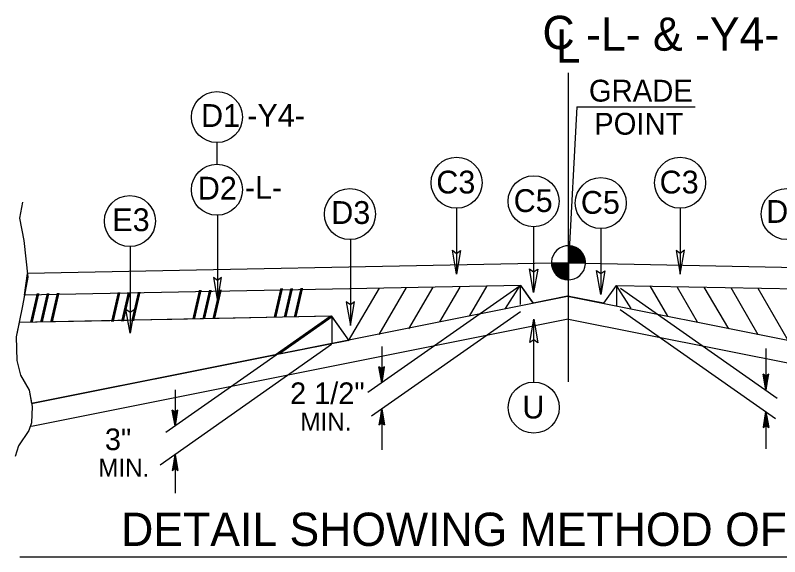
# Model space of a CAD drawing. Extents: x 1904401 to 1905163, y 193929 to 194736.
# Drawn here: x 1904976.61 to 1905019.98, y 194607.17 to 194637.9 of the extents above; entities that cross this region are included whole.
import ezdxf

# ---------------------------------------------------------------- set-up
doc = ezdxf.new("R2010")
doc.units = 0
for name, color, linetype in [('Old_Level_1', 7, 'Continuous'), ('Old_Level_11', 7, 'Continuous'), ('Old_Level_2', 7, 'Continuous'), ('Old_Level_20', 7, 'Continuous'), ('Old_Level_21', 7, 'Continuous'), ('Old_Level_3', 7, 'Continuous'), ('Prop Shade Medium', 7, 'Continuous')]:
    doc.layers.add(name, color=color, linetype=linetype)

msp = doc.modelspace()

# ---------------------------------------------------------------- linework, layer by layer
at = {"layer": 'Old_Level_1'}
for p, q in [((1905007.984, 194617.085), (1905007.984, 194634.631)), ((1905007.991, 194623.852), (1905007.991, 194624.817)), ((1905007.024, 194623.852), (1905007.991, 194623.852)), ((1905007.991, 194623.852), (1905007.991, 194622.885)), ((1905008.959, 194623.852), (1905007.991, 194623.852)), ((1905007.991, 194622.885), (1905007.991, 194623.852)), ((1905007.985, 194622.885), (1905007.985, 194623.841)), ((1905005.257, 194622.546), (1904996.612, 194616.491)), ((1904997.244, 194622.408), (1904995.5, 194619.42)), ((1904998.775, 194622.44), (1904997.232, 194619.789)), ((1905000.291, 194622.469), (1904998.906, 194620.095)), ((1905001.819, 194622.466), (1905000.671, 194620.5)), ((1905003.358, 194622.545), (1905002.358, 194620.829)), ((1905010.934, 194622.406), (1905019.841, 194616.168)), ((1905012.61, 194622.545), (1905013.612, 194620.829)), ((1905014.15, 194622.466), (1905015.298, 194620.5)), ((1905015.677, 194622.469), (1905017.064, 194620.095)), ((1905017.194, 194622.44), (1905018.738, 194619.789)), ((1905018.726, 194622.408), (1905020.444, 194619.464)), ((1904994.56, 194620.816), (1904976.825, 194620.461)), ((1904994.56, 194620.816), (1904985.144, 194614.222)), ((1904995.525, 194619.461), (1904994.56, 194620.816)), ((1904994.56, 194620.816), (1904994.56, 194619.269)), ((1905005.278, 194621.067), (1904996.817, 194615.143)), ((1905010.922, 194621.193), (1905019.742, 194615.018)), ((1905007.973, 194620.653), (1904977.518, 194614.562)), ((1905007.996, 194620.653), (1905038.521, 194614.547)), ((1904994.553, 194619.22), (1904984.818, 194612.369)), ((1904994.56, 194619.271), (1904991.472, 194618.653)), ((1904997.399, 194619.1), (1904997.399, 194617.044)), ((1904991.472, 194618.653), (1904977.529, 194615.864)), ((1905019.19, 194618.982), (1905019.19, 194616.625)), ((1904997.399, 194617.044), (1904997.24, 194617.946)), ((1904997.399, 194617.828), (1904997.24, 194617.946)), ((1904997.399, 194617.044), (1904997.263, 194617.929)), ((1904997.285, 194617.911), (1904997.399, 194617.044)), ((1904997.399, 194617.044), (1904997.308, 194617.896)), ((1904997.331, 194617.879), (1904997.399, 194617.044)), ((1904997.399, 194617.044), (1904997.354, 194617.862)), ((1904997.377, 194617.845), (1904997.399, 194617.044)), ((1904997.399, 194617.044), (1904997.559, 194617.946)), ((1904997.559, 194617.946), (1904997.399, 194617.828)), ((1904997.537, 194617.929), (1904997.399, 194617.044)), ((1904997.399, 194617.044), (1904997.512, 194617.911)), ((1904997.489, 194617.896), (1904997.399, 194617.044)), ((1904997.399, 194617.044), (1904997.467, 194617.879)), ((1904997.444, 194617.862), (1904997.399, 194617.044)), ((1904997.399, 194617.044), (1904997.421, 194617.845)), ((1904997.399, 194617.828), (1904997.399, 194617.044)), ((1905019.19, 194616.625), (1905019.032, 194617.527)), ((1905019.19, 194617.409), (1905019.032, 194617.527)), ((1905019.19, 194616.625), (1905019.053, 194617.51)), ((1905019.076, 194617.493), (1905019.19, 194616.625)), ((1905019.19, 194616.625), (1905019.099, 194617.476)), ((1905019.122, 194617.459), (1905019.19, 194616.625)), ((1905019.19, 194616.625), (1905019.144, 194617.443)), ((1905019.166, 194617.427), (1905019.19, 194616.625)), ((1905019.19, 194616.625), (1905019.35, 194617.527)), ((1905019.35, 194617.527), (1905019.19, 194617.409)), ((1905019.326, 194617.51), (1905019.19, 194616.625)), ((1905019.19, 194616.625), (1905019.303, 194617.493)), ((1905019.281, 194617.476), (1905019.19, 194616.625)), ((1905019.19, 194616.625), (1905019.258, 194617.459)), ((1905019.235, 194617.443), (1905019.19, 194616.625)), ((1905019.19, 194616.625), (1905019.214, 194617.427)), ((1905019.19, 194617.409), (1905019.19, 194616.625)), ((1904985.674, 194616.642), (1904985.674, 194614.591)), ((1904985.674, 194614.591), (1904985.513, 194615.494)), ((1904985.674, 194615.378), (1904985.513, 194615.494)), ((1904985.674, 194614.591), (1904985.536, 194615.478)), ((1904985.561, 194615.46), (1904985.674, 194614.591)), ((1904985.674, 194614.591), (1904985.584, 194615.444)), ((1904985.606, 194615.428), (1904985.674, 194614.591)), ((1904985.674, 194614.591), (1904985.628, 194615.412)), ((1904985.651, 194615.395), (1904985.674, 194614.591)), ((1904985.674, 194614.591), (1904985.833, 194615.494)), ((1904985.833, 194615.494), (1904985.674, 194615.378)), ((1904985.81, 194615.478), (1904985.674, 194614.591)), ((1904985.674, 194614.591), (1904985.788, 194615.46)), ((1904985.765, 194615.444), (1904985.674, 194614.591)), ((1904985.674, 194614.591), (1904985.741, 194615.428)), ((1904985.72, 194615.412), (1904985.674, 194614.591)), ((1904985.674, 194614.591), (1904985.697, 194615.395)), ((1904985.674, 194615.378), (1904985.674, 194614.591)), ((1904997.399, 194615.551), (1904997.24, 194614.648)), ((1904997.263, 194614.666), (1904997.399, 194615.551)), ((1904997.399, 194615.551), (1904997.285, 194614.682)), ((1904997.308, 194614.7), (1904997.399, 194615.551)), ((1904997.399, 194615.551), (1904997.331, 194614.716)), ((1904997.354, 194614.732), (1904997.399, 194615.551)), ((1904997.399, 194615.551), (1904997.377, 194614.749)), ((1904997.399, 194615.551), (1904997.399, 194613.234)), ((1904997.399, 194615.551), (1904997.559, 194614.648)), ((1904997.399, 194614.765), (1904997.399, 194615.551)), ((1904997.421, 194614.749), (1904997.399, 194615.551)), ((1904997.399, 194615.551), (1904997.444, 194614.732)), ((1904997.467, 194614.716), (1904997.399, 194615.551)), ((1904997.399, 194615.551), (1904997.489, 194614.7)), ((1904997.512, 194614.682), (1904997.399, 194615.551)), ((1904997.399, 194615.551), (1904997.537, 194614.666)), ((1905019.19, 194615.404), (1905019.032, 194614.501)), ((1905019.053, 194614.52), (1905019.19, 194615.404)), ((1905019.19, 194615.404), (1905019.076, 194614.535)), ((1905019.099, 194614.553), (1905019.19, 194615.404)), ((1905019.19, 194615.404), (1905019.122, 194614.569)), ((1905019.144, 194614.585), (1905019.19, 194615.404)), ((1905019.19, 194615.404), (1905019.166, 194614.601)), ((1905019.19, 194615.404), (1905019.19, 194613.294)), ((1905019.19, 194615.404), (1905019.35, 194614.501)), ((1905019.19, 194614.619), (1905019.19, 194615.404)), ((1905019.214, 194614.601), (1905019.19, 194615.404)), ((1905019.19, 194615.404), (1905019.235, 194614.585)), ((1905019.258, 194614.569), (1905019.19, 194615.404)), ((1905019.19, 194615.404), (1905019.281, 194614.553)), ((1905019.303, 194614.535), (1905019.19, 194615.404)), ((1905019.19, 194615.404), (1905019.326, 194614.52)), ((1904997.24, 194614.648), (1904997.399, 194614.765)), ((1904997.399, 194614.765), (1904997.559, 194614.648)), ((1905019.032, 194614.501), (1905019.19, 194614.619)), ((1905019.19, 194614.619), (1905019.35, 194614.501)), ((1904985.674, 194612.97), (1904985.513, 194612.067)), ((1904985.538, 194612.084), (1904985.674, 194612.97)), ((1904985.674, 194612.97), (1904985.561, 194612.101)), ((1904985.584, 194612.117), (1904985.674, 194612.97)), ((1904985.674, 194612.97), (1904985.606, 194612.134)), ((1904985.628, 194612.15), (1904985.674, 194612.97)), ((1904985.674, 194612.97), (1904985.651, 194612.167)), ((1904985.674, 194612.97), (1904985.674, 194610.776)), ((1904985.674, 194612.97), (1904985.833, 194612.067)), ((1904985.674, 194612.184), (1904985.674, 194612.97)), ((1904985.697, 194612.167), (1904985.674, 194612.97)), ((1904985.674, 194612.97), (1904985.72, 194612.15)), ((1904985.743, 194612.134), (1904985.674, 194612.97)), ((1904985.674, 194612.97), (1904985.765, 194612.117)), ((1904985.788, 194612.101), (1904985.674, 194612.97)), ((1904985.674, 194612.97), (1904985.81, 194612.084)), ((1904985.513, 194612.067), (1904985.674, 194612.184)), ((1904985.674, 194612.184), (1904985.833, 194612.067))]:
    msp.add_line(p, q, dxfattribs=at)
for points in [[(1904977.013, 194627.289), (1904976.85, 194626.39), (1904977.096, 194625.112), (1904977.312, 194623.043), (1904977.013, 194621.41), (1904976.66, 194619.641), (1904976.687, 194618.307), (1904976.905, 194617.464), (1904977.396, 194616.619), (1904977.558, 194615.694), (1904977.531, 194614.769), (1904977.368, 194614.332), (1904976.797, 194613.461), (1904976.606, 194612.862)], [(1905008, 194624.817), (1905008, 194624.817), (1905008, 194623.852)], [(1905008.019, 194624.817), (1905008.019, 194623.852)], [(1905008.039, 194624.817), (1905008.039, 194623.852)], [(1905008.058, 194624.816), (1905008.058, 194623.852)], [(1905008.079, 194624.815), (1905008.079, 194623.852)], [(1905008.097, 194624.812), (1905008.097, 194623.852)], [(1905008.117, 194624.811), (1905008.117, 194623.852)], [(1905008.135, 194624.807), (1905008.135, 194623.852)], [(1905008.155, 194624.804), (1905008.155, 194623.852)], [(1905008.174, 194624.8), (1905008.174, 194623.852)], [(1905008.194, 194624.798), (1905008.194, 194623.852)], [(1905008.214, 194624.793), (1905008.214, 194623.852)], [(1905008.233, 194624.788), (1905008.233, 194623.852)], [(1905008.252, 194624.782), (1905008.252, 194623.852)], [(1905008.27, 194624.777), (1905008.27, 194623.852)], [(1905008.289, 194624.771), (1905008.289, 194623.852)], [(1905008.31, 194624.764), (1905008.31, 194623.852)], [(1905008.33, 194624.758), (1905008.33, 194623.852)], [(1905008.349, 194624.75), (1905008.349, 194623.852)], [(1905008.369, 194624.742), (1905008.367, 194623.852)], [(1905008.388, 194624.733), (1905008.388, 194623.852)], [(1905008.406, 194624.725), (1905008.406, 194623.852)], [(1905008.425, 194624.716), (1905008.425, 194623.852)], [(1905008.445, 194624.705), (1905008.445, 194623.852)], [(1905008.464, 194624.693), (1905008.464, 194623.852)], [(1905008.485, 194624.682), (1905008.485, 194623.852)], [(1905008.504, 194624.671), (1905008.503, 194623.852)], [(1905008.523, 194624.66), (1905008.523, 194623.852)], [(1905008.541, 194624.646), (1905008.541, 194623.852)], [(1905008.56, 194624.632), (1905008.56, 194623.852)], [(1905008.581, 194624.618), (1905008.581, 194623.852)], [(1905008.6, 194624.603), (1905008.6, 194623.852)], [(1905008.62, 194624.586), (1905008.62, 194623.852)], [(1905008.639, 194624.57), (1905008.638, 194623.851)], [(1905008.659, 194624.551), (1905008.659, 194623.852)], [(1905008.676, 194624.533), (1905008.676, 194623.851)], [(1905008.696, 194624.512), (1905008.696, 194623.851)], [(1905008.716, 194624.49), (1905008.716, 194623.852)], [(1905008.735, 194624.468), (1905008.735, 194623.851)], [(1905008.756, 194624.444), (1905008.756, 194623.851)], [(1905008.775, 194624.419), (1905008.773, 194623.852)], [(1905008.794, 194624.392), (1905008.794, 194623.851)], [(1905008.812, 194624.361), (1905008.812, 194623.851)], [(1905008.831, 194624.329), (1905008.831, 194623.852)], [(1905008.851, 194624.293), (1905008.851, 194623.851)], [(1905007.029, 194623.852), (1905007.029, 194623.746)], [(1905007.049, 194623.852), (1905007.049, 194623.633)], [(1905007.069, 194623.852), (1905007.069, 194623.563)], [(1905007.089, 194623.852), (1905007.089, 194623.507)], [(1905007.106, 194623.852), (1905007.106, 194623.459)], [(1905007.126, 194623.852), (1905007.126, 194623.419)], [(1905007.145, 194623.852), (1905007.145, 194623.383)], [(1905007.165, 194623.852), (1905007.165, 194623.349)], [(1905007.184, 194623.852), (1905007.184, 194623.319)], [(1905007.205, 194623.852), (1905007.205, 194623.289)], [(1905007.224, 194623.852), (1905007.224, 194623.264)], [(1905007.242, 194623.852), (1905007.242, 194623.24)], [(1905007.261, 194623.852), (1905007.261, 194623.216)], [(1905007.28, 194623.852), (1905007.28, 194623.195)], [(1905007.3, 194623.852), (1905007.3, 194623.175)], [(1905007.319, 194623.852), (1905007.319, 194623.157)], [(1905007.34, 194623.852), (1905007.34, 194623.137)], [(1905007.359, 194623.852), (1905007.358, 194623.12)], [(1905007.377, 194623.852), (1905007.377, 194623.103)], [(1905007.396, 194623.852), (1905007.396, 194623.089)], [(1905007.416, 194623.852), (1905007.416, 194623.075)], [(1905007.436, 194623.852), (1905007.436, 194623.061)], [(1905007.455, 194623.852), (1905007.455, 194623.047)], [(1905007.475, 194623.852), (1905007.475, 194623.034)], [(1905007.494, 194623.852), (1905007.493, 194623.022)], [(1905007.513, 194623.852), (1905007.513, 194623.01)], [(1905007.532, 194623.852), (1905007.532, 194623)], [(1905007.551, 194623.852), (1905007.551, 194622.99)], [(1905007.571, 194623.852), (1905007.571, 194622.98)], [(1905007.591, 194623.852), (1905007.591, 194622.972)], [(1905007.611, 194623.852), (1905007.611, 194622.962)], [(1905007.63, 194623.852), (1905007.629, 194622.956)], [(1905007.648, 194623.852), (1905007.648, 194622.948)], [(1905007.669, 194623.852), (1905007.669, 194622.94)], [(1905007.686, 194623.852), (1905007.686, 194622.934)], [(1905007.706, 194623.852), (1905007.706, 194622.928)], [(1905007.726, 194623.852), (1905007.726, 194622.923)], [(1905007.746, 194623.852), (1905007.746, 194622.917)], [(1905007.765, 194623.852), (1905007.764, 194622.911)], [(1905007.783, 194623.852), (1905007.783, 194622.908)], [(1905007.804, 194623.852), (1905007.803, 194622.904)], [(1905007.821, 194623.852), (1905007.821, 194622.9)], [(1905007.842, 194623.852), (1905007.842, 194622.897)], [(1905007.861, 194623.852), (1905007.861, 194622.893)], [(1905007.882, 194623.852), (1905007.882, 194622.892)], [(1905007.9, 194623.852), (1905007.899, 194622.888)], [(1905007.919, 194623.852), (1905007.919, 194622.888)], [(1905007.939, 194623.852), (1905007.938, 194622.886)], [(1905007.957, 194623.852), (1905007.957, 194622.886)], [(1905007.978, 194623.852), (1905007.978, 194622.885), (1905007.978, 194622.885)], [(1905008.871, 194624.252), (1905008.871, 194623.851)], [(1905008.89, 194624.208), (1905008.89, 194623.852)], [(1905008.909, 194624.153), (1905008.909, 194623.851)], [(1905008.929, 194624.088), (1905008.929, 194623.851)], [(1905008.947, 194623.988), (1905008.947, 194623.852)]]:
    msp.add_lwpolyline(points, dxfattribs=at)
for start, end in [(358.0003, 356.1713), (359.9905, 89.9905), (179.9905, 268.7186), (269.6533, 269.9905)]:
    msp.add_arc((1905007.991, 194623.852), 0.967, start, end, dxfattribs=at)
at = {"layer": 'Old_Level_11'}
for p, q in [((1904988.047, 194630.674), (1904988.047, 194629.442)), ((1905001.641, 194626.951), (1905001.641, 194623.212)), ((1905014.327, 194626.951), (1905014.327, 194623.212)), ((1904988.073, 194626.549), (1904988.073, 194621.671)), ((1905006.014, 194625.899), (1905006.014, 194622.16)), ((1905009.826, 194625.798), (1905009.826, 194622.059)), ((1904995.617, 194625.17), (1904995.617, 194620.292)), ((1904983.121, 194624.77), (1904983.121, 194619.865)), ((1905007.984, 194623.852), (1904977.299, 194623.239)), ((1905007.984, 194623.852), (1905038.671, 194623.239)), ((1905007.987, 194623.852), (1905038.671, 194623.239)), ((1904977.124, 194622.007), (1904977.299, 194623.239)), ((1905005.292, 194622.57), (1904977.124, 194622.007)), ((1905004.42, 194621.257), (1905005.253, 194622.558)), ((1905005.253, 194622.558), (1905005.253, 194621.489)), ((1905005.981, 194621.558), (1905005.292, 194622.57)), ((1905010.699, 194622.57), (1905009.988, 194621.558)), ((1905010.699, 194622.57), (1905038.847, 194622.007)), ((1905011.55, 194621.257), (1905010.717, 194622.558)), ((1905010.717, 194622.558), (1905010.717, 194621.38)), ((1905005.292, 194622.536), (1905005.981, 194621.558)), ((1905008.03, 194621.966), (1904977.529, 194615.864)), ((1905007.939, 194621.966), (1905005.981, 194621.558)), ((1905007.939, 194621.966), (1905038.442, 194615.864)), ((1905009.988, 194621.558), (1905007.939, 194621.966)), ((1905006.021, 194617.081), (1905006.021, 194620.659)), ((1904976.866, 194607.166), (1905040.469, 194607.166))]:
    msp.add_line(p, q, dxfattribs=at)
for points in [[(1905001.872, 194624.551), (1905001.641, 194623.212), (1905001.403, 194624.559), (1905001.641, 194624.388)], [(1905014.095, 194624.551), (1905014.327, 194623.212), (1905014.565, 194624.559), (1905014.327, 194624.388)], [(1905006.245, 194623.499), (1905006.014, 194622.16), (1905005.776, 194623.507), (1905006.014, 194623.336)], [(1904987.843, 194623.01), (1904988.073, 194621.671), (1904988.311, 194623.018), (1904988.073, 194622.846)], [(1905010.058, 194623.398), (1905009.826, 194622.059), (1905009.588, 194623.406), (1905009.826, 194623.235)], [(1904995.387, 194621.632), (1904995.617, 194620.292), (1904995.856, 194621.639), (1904995.617, 194621.468)], [(1904983.351, 194621.204), (1904983.121, 194619.865), (1904982.883, 194621.212), (1904983.121, 194621.041)], [(1905005.79, 194619.32), (1905006.021, 194620.659), (1905006.26, 194619.313), (1905006.021, 194619.484)]]:
    msp.add_lwpolyline(points, close=True, dxfattribs=at)
for centre in [(1904988.047, 194632.121), (1905001.641, 194628.397), (1905014.326, 194628.397), (1904988.047, 194627.996), (1905006.014, 194627.345), (1905009.827, 194627.244), (1904995.591, 194626.617), (1905020.377, 194626.617), (1904983.106, 194626.217), (1905006.021, 194615.634)]:
    msp.add_circle(centre, 1.447, dxfattribs=at)
at = {"layer": 'Old_Level_3'}
for q in [(1905007.987, 194623.852), (1905015.182, 194632.704)]:
    msp.add_line((1905008.46, 194632.704), q, dxfattribs=at)
at = {"layer": 'Prop Shade Medium'}
for p, q in [((1904994.474, 194620.814), (1904985.494, 194620.635)), ((1904991.35, 194618.627), (1904994.474, 194620.814)), ((1904976.825, 194620.461), (1904976.66, 194619.641)), ((1904982.994, 194620.585), (1904976.825, 194620.461)), ((1904977.528, 194615.864), (1904991.35, 194618.627))]:
    msp.add_line(p, q, dxfattribs=at)
for points in [[(1904985.494, 194620.635), (1904983.245, 194620.59), (1904983.121, 194619.865), (1904982.994, 194620.585)], [(1904976.66, 194619.641), (1904976.687, 194618.307), (1904976.905, 194617.464)], [(1904976.905, 194617.464), (1904977.396, 194616.619), (1904977.528, 194615.864)]]:
    msp.add_lwpolyline(points, dxfattribs=at)
msp.add_lwpolyline([(1904995.525, 194619.461), (1904994.588, 194620.777), (1904991.589, 194618.677)], close=True, dxfattribs=at)

# ---------------------------------------------------------------- texts
at = {"layer": 'Old_Level_1'}
for height, rotation, p in [(1.5388, 1.1447, (1904977.436, 194620.483)), (1.5388, 1.1464, (1904982.035, 194620.537)), (1.5382, 1.1445, (1904986.644, 194620.672)), (1.5383, 1.1463, (1904991.258, 194620.767))]:
    msp.add_text('/// ', height=height, rotation=rotation, dxfattribs=at).set_placement(p)
at = {"layer": 'Old_Level_11'}
for s, p in [('GRADE', (1905009.151, 194633.003)), ('POINT', (1905009.45, 194631.124))]:
    msp.add_text(s, height=1.2398, dxfattribs=at).set_placement(p)
at = {"layer": 'Old_Level_2'}
msp.add_text('C', height=1.89, dxfattribs=at).set_placement((1905006.516, 194635.984))
msp.add_text('L', height=1.89, rotation=359.9469, dxfattribs=at).set_placement((1905007.276, 194635.221))
at = {"layer": 'Old_Level_20'}
for s, height, p in [('-L- & -Y4-', 1.89, (1905008.991, 194635.891)), ('D1', 1.2949, (1904987.147, 194631.565)), ('C3', 1.2949, (1905000.493, 194627.786)), ('C3', 1.2949, (1905013.163, 194627.786)), ('D2', 1.2949, (1904986.962, 194627.44)), ('C5', 1.2949, (1905004.882, 194626.734)), ('C5', 1.2949, (1905008.694, 194626.633)), ('D3', 1.2949, (1904994.532, 194626.057)), ('D3', 1.2949, (1905019.207, 194626.118)), ('E3', 1.2949, (1904982.112, 194625.647)), ('2 1/2"', 1.2268, (1904992.196, 194615.833)), ('U', 1.295, (1905005.374, 194615.012)), ('3"', 1.2268, (1904981.69, 194613.217))]:
    msp.add_text(s, height=height, dxfattribs=at).set_placement(p)
for s, p in [('-Y4-', (1904989.767, 194631.571)), ('-L-', (1904989.632, 194627.484))]:
    msp.add_text(s, height=1.2949, rotation=360, dxfattribs=at).set_placement(p)
at = {"layer": 'Old_Level_21'}
for s, height, p in [('MIN.', 1.0252, (1904992.785, 194614.325)), ('MIN.', 1.0252, (1904981.314, 194611.709)), ('DETAIL SHOWING METHOD OF WEDGING', 1.89, (1904982.614, 194607.778))]:
    msp.add_text(s, height=height, dxfattribs=at).set_placement(p)

doc.saveas('drawing.dxf')
